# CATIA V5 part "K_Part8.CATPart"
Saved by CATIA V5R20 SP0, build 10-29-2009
Part number: Part8
Bounding box of the stored display mesh (mm): x -1 to 1, y 68.049 to 69.999, z -743 to -68
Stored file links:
  G:\Khaled_CFAO_2011\SIL\SIL_GR2\ctanaphiko\Khaled\CAD_ThinkMOTION\K_Part8.CATPart
  G:\Khaled_CFAO_2011\SIL\SIL_GR2\ctanaphiko\CATIA\ctanaphiko.CATProduct
  G:\Khaled_CFAO_2011\SIL\SIL_GR2\ctanaphiko\Khaled\CAD_ThinkMOTION\K_Leg_Level2.CATPart
  G:\Khaled_CFAO_2011\SIL\SIL_GR2\ctanaphiko\CATIA\Squelette.CATPart
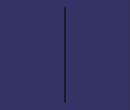
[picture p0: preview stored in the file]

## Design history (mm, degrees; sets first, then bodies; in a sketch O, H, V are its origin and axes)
AxisSystem1: origin (0, 0, 0), X (1, 0, 0), Y (0, 1, 0), Z (0, 0, 1)
Set1
  Plane1 "Plan_S1": linked copy from another document
  DatumCurve1: linked copy from another document
  DatumPoint1: linked copy from another document
Body1 (main body)
  Sketch1 on Plane1, origin (0, 0, -68), H (1, 0, 0), V (0, 1, 0)
    circle A1 centre (0, 69.024) radius 1
    point P1 (0, 69.024)
    reference projected point E1 (0, 69.024) from vertex of DatumPoint1
    radius A1 = 1
    coincidence: P1 E1
  Rib1: profile Sketch1, centre curve DatumCurve1, thin wall 0.5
